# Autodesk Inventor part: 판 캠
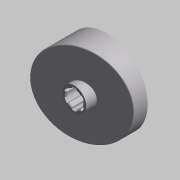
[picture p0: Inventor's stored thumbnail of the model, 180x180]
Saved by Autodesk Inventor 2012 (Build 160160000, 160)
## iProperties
Company: 한국ATC센터
Created: 2014-07
Part Number: 판 캠
Document SubType Name: 모델링
Designer: KYOUNG IL JANG
Material: 강, 연강
Mass: 682.454 g
Surface Area: 331.302 cm^2
Volume: 86.8262 cm^3
Density: 7.86 g/cm^3
변환 표준: STEP AP214IS
파일 이름: C:\Users\SeoGD\Desktop\?쒗뿕\??stp
전처리기: Build: 253, Release: 2010 SP1 - Date: Wed 07/29/2009
전송 단위: 밀리미터
불확실성: 0.01
Author: KYOUNG IL JANG
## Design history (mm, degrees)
node "작업 평면4"
sketch "스케치1"
  geometry: C1 r 44.5 at (0, 0); 1 further point
  constraints: 1 centre point, 1 coincident
  dimensions: "d25" = 89 diameter of C1
extrude "돌출1" new body sketch "스케치1" distance "d1" = 40; taper "d2" = 0 deg
sketch "스케치2"
  geometry: L1 (-44.5, 15)-(44.5, 38.847); L2 (-44.5, 0)-(-44.5, 40) reference; L3 (-44.5, 40)-(44.5, 40) reference; L4 (44.5, 0)-(44.5, 40) reference; 1 further point
  constraints: 2 end point, 2 point on line
  dimensions: "d26" = 15 distance of L2.start L1.start; "d27" = 75 deg angle of L1 L2
extrude "돌출2" cut sketch "스케치2" stored distance "d5" = 40; taper "d6" = 0 deg
node "작업 평면1"
sketch "스케치3"
  geometry: C1 r 13 at (0, 0); 1 further point
  constraints: 1 centre point, 1 coincident
  dimensions: "d9" = 26 diameter of C1
extrude "돌출3" join sketch "스케치3" distance "d10" = 38; taper "d11" = 0 deg
hole "구멍1" diameter "d14" = 18; stored, may be unused: countersink angle "d18" = 90 deg, drill point angle "d20" = 118 deg; dims "d12" = 10, "d13" = 10, "d15" = 6, "d16" = 4, "d17" = 2, "d19" = 8
feature "쉘2" dims "d29" = 5
sketch "스케치6"
  geometry: C1 r 17.5 at (0, 0); C2 r 14 at (0, 0) reference; 1 further point
  constraints: 1 centre point, 1 coincident
  dimensions: "d28" = 35 diameter of C1
extrude "돌출4" join sketch "스케치6" stored distance "d30" = 38; taper "d31" = 0 deg
fillet "모깎기1" dims "d32" = 3
chamfer "모따기1" distance "d21" = 1; stored, may be unused: second distance "d22" = 2, angle "d23" = 45 deg
sketch "스케치7"
  geometry: L1 (-12.374, 12.374)-(-27.931, 27.931); A1 r 39.5 centre (0, 0) between (-27.931, 27.931) and (0, 39.5) reference; 2 further points
  constraints: 2 end point, 2 point on circle, 1 point on line, 1 vertical alignment, 2 other
  dimensions: "d33" = 45 deg dimension on point (0, 0) L1.start A1.end
feature "리브1" sketch "스케치7" dims "d34" = 5, "d35" = 1, "d36" = 0
fillet "모깎기2" dims "d37" = 3
sketch "스케치8"
  geometry: L1 (2.5, 10.712)-(2.5, 8.646); L2 (-2.5, 10.712)-(-2.5, 8.646); A1 r 11 centre (0, 0) between (2.5, 10.712) and (-2.5, 10.712); A2 r 9 centre (0, 0) between (2.5, 8.646) and (-2.5, 8.646) reference; 1 further point
  constraints: 4 end point, 4 point on circle, 2 parallel, 1 centre point, 1 coincident, 1 vertical
  dimensions: "d41" = 22 diameter of A1; "d42" = 5 distance between parallel lines of L1 L2
extrude "돌출5" cut sketch "스케치8" stored distance "d43" = 38; taper "d44" = 0 deg
fillet "모깎기3" dims "d48" = 1
node "솔리드1"
node "솔리드 본체"
node "곡면 본체"
pattern_circular "원형 패턴1" dims angle "d39" = 360 deg
pattern_circular "원형 패턴2" dims angle "d46" = 360 deg
node "솔리드2"
